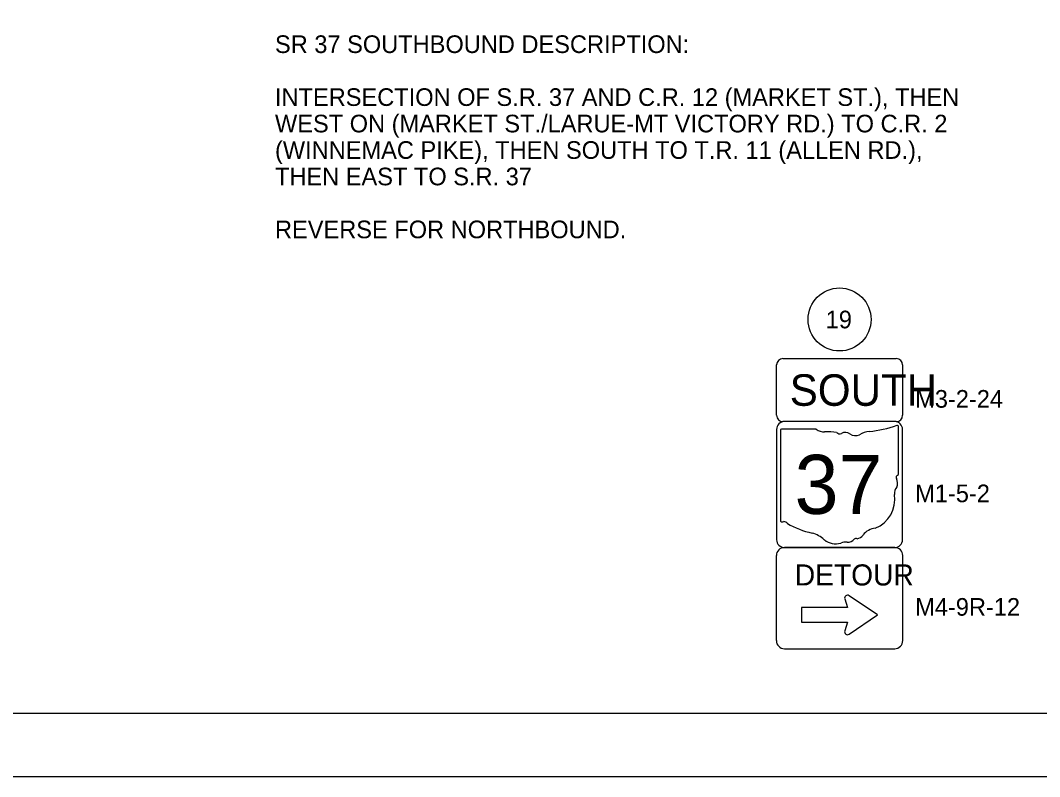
# Model space of a CAD drawing. Extents: x 0 to 680, y 0 to 440.
# Drawn here: x 170.3 to 332.1, y 0 to 120 of the extents above; entities that cross this region are included whole.
import ezdxf

# ---------------------------------------------------------------- set-up
doc = ezdxf.new("R2010")
doc.units = 0
for name, color, linetype in [('GM_X_State_Location', 7, 'Continuous'), ('SH_Border', 7, 'Continuous'), ('SH_Cut_Line', 7, 'Continuous'), ('SH_Text', 7, 'Continuous'), ('SN_P_Signs', 7, 'Continuous'), ('SN_P_Text', 7, 'Continuous')]:
    doc.layers.add(name, color=color, linetype=linetype)

msp = doc.modelspace()

# ---------------------------------------------------------------- linework, layer by layer
at = {"layer": 'SH_Border'}
msp.add_lwpolyline([(30, 430), (670, 430), (670, 10), (30, 10)], close=True, dxfattribs=at)
at = {"layer": 'SH_Cut_Line'}
msp.add_lwpolyline([(0, 0), (680, 0), (680, 440), (0, 440)], close=True, dxfattribs=at)
at = {"layer": 'SN_P_Signs'}
for p, q in [((291.32, 66.36), (309.32, 66.36)), ((290.32, 57.36), (290.32, 65.36)), ((310.32, 65.36), (310.32, 57.36)), ((296.61, 55.17), (291.11, 55.17)), ((309.32, 56.36), (291.32, 56.36)), ((309.68, 48.08), (309.68, 55.52)), ((290.93, 54.92), (290.93, 40.69)), ((309.68, 48.08), (309.68, 48.08)), ((301.14, 28.2), (301.57, 26.83)), ((306.34, 25.67), (301.83, 28.72)), ((301.57, 26.83), (294.3, 26.83)), ((294.3, 26.83), (294.3, 24.49)), ((294.3, 24.49), (301.57, 24.49)), ((301.57, 24.49), (301.14, 23.13)), ((301.83, 22.61), (306.34, 25.67))]:
    msp.add_line(p, q, dxfattribs=at)
for points in [[(290.32, 55.11), (290.32, 37.61)], [(309.07, 56.36), (291.57, 56.36)], [(310.32, 37.61), (310.32, 55.11)], [(291.57, 36.36), (309.07, 36.36)], [(309.07, 36.36), (291.57, 36.36)], [(290.28, 35.08), (290.28, 21.59)], [(310.35, 21.59), (310.35, 35.08)], [(291.57, 20.31), (309.07, 20.31)]]:
    msp.add_lwpolyline(points, dxfattribs=at)
msp.add_circle((300.32, 72.56), 5, dxfattribs=at)
for centre, radius, start, end in [((291.32, 65.36), 1, 90, 180), ((309.32, 65.36), 1, 0, 90), ((291.32, 57.36), 1, 180, 270), ((309.32, 57.36), 1, 270, 0), ((291.57, 55.11), 1.25, 90, 180), ((291.14, 54.95), 0.217, 98.1301, 188.1301), ((297.91, 56.82), 2.11, 231.6195, 271.1119), ((303, 74.57), 19.88, 275.8445, 288.9065), ((309.07, 55.11), 1.25, 0, 90), ((309.47, 55.55), 0.209, 351.8621, 97.738), ((298.61, 47.18), 7.56, 80.4867, 94.9883), ((300.33, 55.03), 0.608, 219.7921, 297.1024), ((301.22, 53.38), 1.26, 54.4667, 119.1411), ((302.85, 55.64), 1.52, 233.8562, 294.8282), ((305.54, 50.82), 4, 97.3462, 120.7689), ((309.63, 47.53), 0.323, 107.944, 210.337), ((307.58, 46.59), 1.94, 340.033, 23.6496), ((309.46, 48.05), 0.223, 289.6038, 7.7341), ((310.43, 44.96), 1.41, 136.8065, 186.9296), ((304.11, 44.01), 4.97, 292.3089, 8.9858), ((291.15, 40.66), 0.219, 171.9584, 258.3066), ((291.18, 42.12), 1.67, 267.339, 280.6039), ((291.52, 39.87), 0.603, 29.7484, 93.2717), ((299.13, 52.66), 14.36, 240.4129, 257.1985), ((306.21, 36.7), 2.72, 94.4031, 142.5768), ((291.57, 37.61), 1.25, 180, 270), ((294.85, 34.3), 4.49, 47.1842, 75.836), ((299.71, 39.8), 2.85, 230.7004, 286.2918), ((301.36, 34.88), 2.34, 85.6951, 111.2099), ((301.57, 38.73), 1.52, 268.777, 315.5493), ((302.94, 37.36), 0.428, 65.7517, 132.6484), ((302.76, 39.31), 1.61, 282.8732, 323.2771), ((309.07, 37.61), 1.25, 270, 0), ((291.57, 35.08), 1.28, 90, 180), ((309.07, 35.08), 1.28, 0, 90), ((301.57, 28.34), 0.459, 55.8031, 197.8008), ((301.57, 22.99), 0.459, 162.1992, 304.1969), ((291.57, 21.59), 1.28, 180, 270), ((309.07, 21.59), 1.28, 270, 0)]:
    msp.add_arc(centre, radius, start, end, dxfattribs=at)

# ---------------------------------------------------------------- texts
at = {"layer": 'GM_X_State_Location'}
msp.add_text('95', height=0.01, rotation=0, dxfattribs=at).set_placement((204.29, 104.79))
at = {"layer": 'SH_Text'}
for s, p in [('SR 37 SOUTHBOUND DESCRIPTION:', (210.72, 114.86)), ('INTERSECTION OF S.R. 37 AND C.R. 12 (MARKET ST.), THEN', (210.72, 106.46)), ('WEST ON (MARKET ST./LARUE-MT VICTORY RD.) TO C.R. 2', (210.72, 102.26)), ('(WINNEMAC PIKE), THEN SOUTH TO T.R. 11 (ALLEN RD.),', (210.72, 98.06)), ('THEN EAST TO S.R. 37', (210.72, 93.86)), ('REVERSE FOR NORTHBOUND.', (210.72, 85.46))]:
    msp.add_text(s, height=2.8, dxfattribs=at).set_placement(p)
at = {"layer": 'SN_P_Signs'}
for s, height, p in [('19', 2.8, (298.12, 71.16)), ('SOUTH', 5, (292.41, 58.86)), ('37', 9.375, (293.18, 41.7)), ('DETOUR', 3.345, (293.22, 30.34))]:
    msp.add_text(s, height=height, dxfattribs=at).set_placement(p)
at = {"layer": 'SN_P_Text'}
for s, p in [('M3-2-24', (312.32, 58.56)), ('M1-5-2', (312.32, 43.56)), ('M4-9R-12', (312.32, 25.54))]:
    msp.add_text(s, height=2.8, dxfattribs=at).set_placement(p)

doc.saveas('drawing.dxf')
